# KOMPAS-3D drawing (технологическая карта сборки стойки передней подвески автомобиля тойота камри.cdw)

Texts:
  ЄЄЄЄЄЄЄЄЄЄЄЄ
  ȂȂȂȂ̂̃̃ЃЄЄЄЄāāāāā
  ЄЄЄЄЄЄЄ
  ЄЄЄ
  ЄЄЄЄЄЄЄЄЄЄЄЄЄЄЄЄЄЄЄЄЄЄЄЄЄЄ
Dimensions and other numbers on the sheet: 4; 7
